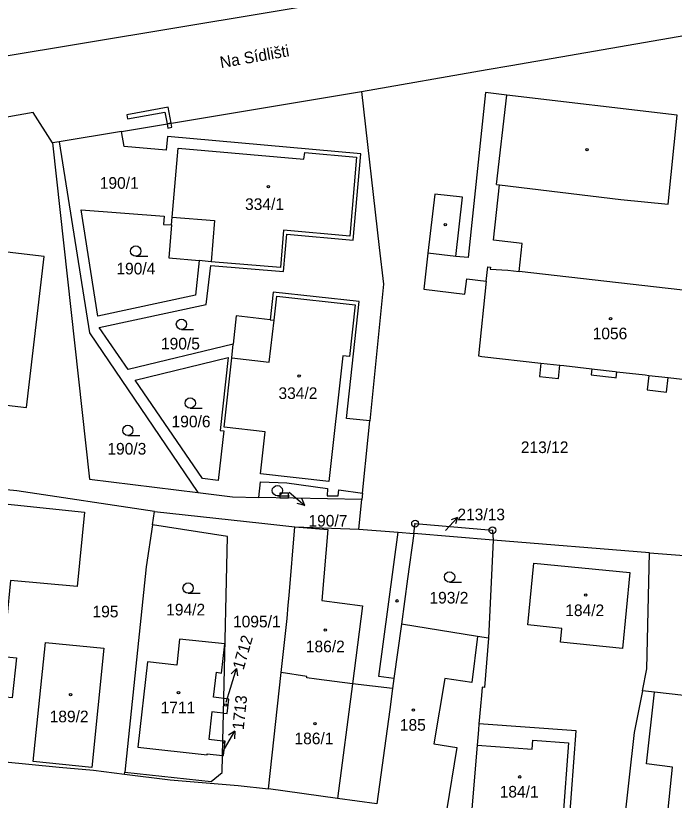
# Model space of a CAD drawing. Extents: x -680203 to -673936, y -1102717 to -1093650.
# Drawn here: x -679068.7 to -678972.5, y -1098436.4 to -1098321.8 of the extents above; entities that cross this region are included whole.
import ezdxf

# ---------------------------------------------------------------- set-up
doc = ezdxf.new("R2010")
doc.units = 0
for name, color, linetype in [('SOxx02xx_Koleje_param další_Popis10', 7, 'Continuous'), ('SOxx02xx_Staničení_Popis10', 7, 'Continuous'), ('SOxxxxxx_Koleje_hlavní_body_Popis10', 7, 'Continuous'), ('SOxxxxxx_Koleje_LN_parametry_Popis10', 7, 'Continuous'), ('SOxxxxxx_Koleje_param další_Popis10', 7, 'Continuous'), ('SOxxxxxx_Osa_bod_P', 7, 'Continuous'), ('SOxxxxxx_Staničení_Popis10', 7, 'Continuous'), ('x_prac', 7, 'Continuous')]:
    doc.layers.add(name, color=color, linetype=linetype)

msp = doc.modelspace()

# ---------------------------------------------------------------- linework, layer by layer
at = {"layer": 'SOxx02xx_Koleje_param další_Popis10'}
for centre, radius in [((-679010.34, -1098396.03), 0.5), ((-679010.34, -1098396.03), 0.0303), ((-678999.04, -1098396.99), 0.5), ((-678999.04, -1098396.99), 0.0303)]:
    msp.add_circle(centre, radius, dxfattribs=at)
at = {"layer": 'SOxx02xx_Staničení_Popis10'}
for p, q in [((-679028.73, -1098391.41), (-679026.46, -1098393.38)), ((-679026.46, -1098393.38), (-679027.55, -1098393.1)), ((-679026.46, -1098393.38), (-679026.89, -1098392.34)), ((-679005.89, -1098397.03), (-679004.16, -1098395.11)), ((-679004.16, -1098395.11), (-679005.06, -1098395.46)), ((-679004.16, -1098395.11), (-679004.42, -1098396.04)), ((-679037.32, -1098420.05), (-679036.44, -1098417.18)), ((-679036.44, -1098417.18), (-679037.21, -1098417.99)), ((-679036.44, -1098417.18), (-679036.26, -1098418.28)), ((-679037.96, -1098422.13), (-679037.32, -1098420.05)), ((-679038.17, -1098428.93), (-679036.67, -1098426.33)), ((-679036.67, -1098426.33), (-679037.6, -1098426.95)), ((-679036.67, -1098426.33), (-679036.74, -1098427.45)), ((-679038.38, -1098429.28), (-679038.17, -1098428.93))]:
    msp.add_line(p, q, dxfattribs=at)
at = {"layer": 'SOxxxxxx_Koleje_hlavní_body_Popis10'}
for p, q in [((-679051.15, -1098356.96), (-679049.4, -1098356.96)), ((-679044.47, -1098367.66), (-679042.72, -1098367.66)), ((-679043.18, -1098379.16), (-679041.43, -1098379.16)), ((-679052.3, -1098383.15), (-679050.55, -1098383.15)), ((-679030.46, -1098391.96), (-679028.71, -1098391.96)), ((-679005.3, -1098404.57), (-679003.55, -1098404.57)), ((-679043.5, -1098406.19), (-679041.75, -1098406.19))]:
    msp.add_line(p, q, dxfattribs=at)
for centre in [(-679051.15, -1098356.21), (-679044.47, -1098366.91), (-679043.18, -1098378.41), (-679052.3, -1098382.4), (-679030.46, -1098391.21), (-679005.3, -1098403.82), (-679043.5, -1098405.44)]:
    msp.add_circle(centre, 0.75, dxfattribs=at)
at = {"layer": 'SOxxxxxx_Koleje_LN_parametry_Popis10'}
for points in [[(-679046.89, -1098335.9), (-679046.56, -1098337.63), (-679045.97, -1098337.53), (-679046.41, -1098335.2), (-679052.46, -1098336.32), (-679052.35, -1098336.91)], [(-679046.56, -1098337.63), (-679046.45, -1098338.24), (-679045.86, -1098338.13), (-679045.97, -1098337.53)], [(-679028.85, -1098392.28), (-679028.85, -1098391.6), (-679030.12, -1098391.57), (-679030.12, -1098392.25)]]:
    msp.add_lwpolyline(points, close=True, dxfattribs=at)
at = {"layer": 'SOxxxxxx_Koleje_param další_Popis10'}
for centre, radius in [((-678985.22, -1098341.4), 0.175), ((-679031.77, -1098346.82), 0.175), ((-679005.94, -1098352.35), 0.175), ((-678981.8, -1098366.08), 0.175), ((-679027.28, -1098374.48), 0.175), ((-679012.98, -1098407.31), 0.175), ((-678985.42, -1098406.47), 0.175), ((-679023.47, -1098411.58), 0.175), ((-679060.67, -1098421.03), 0.175), ((-679044.9, -1098420.71), 0.175), ((-679038, -1098422.54), 0.175), ((-679010.59, -1098423.26), 0.175), ((-679024.97, -1098425.23), 0.175), ((-679038.27, -1098428.02), 0.117), ((-678995.06, -1098433.02), 0.175)]:
    msp.add_circle(centre, radius, dxfattribs=at)
at = {"layer": 'SOxxxxxx_Staničení_Popis10'}
for p, q in [((-678998.45, -1098346.51), (-678996.96, -1098333.42)), ((-678998.45, -1098346.51), (-678998.03, -1098346.56)), ((-679045.84, -1098351.25), (-679039.64, -1098351.77)), ((-679039.64, -1098351.77), (-679040.14, -1098357.76)), ((-679004.4, -1098356.99), (-679008.46, -1098356.53)), ((-678999.96, -1098360.61), (-678999.74, -1098358.5)), ((-678999.74, -1098358.5), (-678999.35, -1098358.54)), ((-678999.35, -1098358.54), (-678999.38, -1098358.84)), ((-678999.38, -1098358.84), (-678996.79, -1098359.01)), ((-678996.79, -1098359.01), (-678995.13, -1098359.2)), ((-679031.64, -1098372.44), (-679030.93, -1098366.31)), ((-679037.11, -1098371.83), (-679031.64, -1098372.44)), ((-678991.98, -1098372.57), (-678989.18, -1098372.89)), ((-678984.51, -1098373.42), (-678984.14, -1098373.46)), ((-678984.14, -1098373.46), (-678981.14, -1098373.8)), ((-678981.14, -1098373.8), (-678980.89, -1098373.83)), ((-678976.19, -1098374.37), (-678973.39, -1098374.69)), ((-679027.93, -1098396.48), (-679023.09, -1098396.88)), ((-679023.09, -1098396.88), (-679023.98, -1098407.26)), ((-679015.66, -1098418.35), (-679012.84, -1098397.28)), ((-678993.88, -1098410.83), (-678992.98, -1098401.79)), ((-678992.98, -1098401.79), (-678978.96, -1098403.19)), ((-678978.96, -1098403.19), (-678980.06, -1098414.26)), ((-679023.98, -1098407.26), (-679018.04, -1098408.05)), ((-679018.04, -1098408.05), (-679019.51, -1098419.41)), ((-678988.9, -1098411.33), (-678993.88, -1098410.83)), ((-678989.11, -1098413.35), (-678988.9, -1098411.33)), ((-679001.23, -1098412.51), (-679002.07, -1098419.22)), ((-678980.06, -1098414.26), (-678989.11, -1098413.35)), ((-679013.43, -1098418.65), (-679015.66, -1098418.35)), ((-679006.01, -1098418.67), (-679007.62, -1098428.18)), ((-679002.07, -1098419.22), (-679006.01, -1098418.67)), ((-679019.51, -1098419.41), (-679021.67, -1098436.17)), ((-678976.53, -1098431.13), (-678975.39, -1098420.63)), ((-679040.01, -1098423.52), (-679040.46, -1098427.53)), ((-679039.24, -1098423.6), (-679040.01, -1098423.52)), ((-679038.33, -1098423.71), (-679039.24, -1098423.6)), ((-679040.46, -1098427.53), (-679038.42, -1098427.76)), ((-678993.24, -1098428.96), (-678993.15, -1098427.66)), ((-678993.15, -1098427.66), (-678987.96, -1098428.03)), ((-679007.62, -1098428.18), (-679004.24, -1098428.75)), ((-679004.24, -1098428.75), (-679005.78, -1098437.99)), ((-679001.27, -1098428.38), (-678993.24, -1098428.96)), ((-678987.96, -1098428.03), (-678988.84, -1098439.94)), ((-678972.77, -1098431.58), (-678976.53, -1098431.13)), ((-678973.79, -1098441.67), (-678972.77, -1098431.58))]:
    msp.add_line(p, q, dxfattribs=at)
at = {"layer": 'x_prac'}
for p, q in [((-679053.23, -1098338.74), (-679018.19, -1098332.92)), ((-679053.23, -1098338.74), (-679062.31, -1098340.25)), ((-679062.31, -1098340.25), (-679063.29, -1098340.41)), ((-679018.12, -1098392.5), (-679033.18, -1098392.19)), ((-679018.03, -1098391.58), (-679018.12, -1098392.5)), ((-679018.55, -1098396.82), (-679018.12, -1098392.5)), ((-679048.69, -1098396.22), (-679048.39, -1098394.25)), ((-679027.93, -1098396.48), (-679018.55, -1098396.82)), ((-678998.95, -1098398.42), (-679010.54, -1098397.47)), ((-678998.95, -1098398.42), (-678999.64, -1098412.76)), ((-678976.11, -1098400.28), (-678998.95, -1098398.42)), ((-678976.11, -1098400.28), (-678962.43, -1098401.4)), ((-679031.77, -1098434.76), (-679029.91, -1098417.79)), ((-679038.33, -1098423.71), (-679038.28, -1098421.57)), ((-679038.42, -1098427.76), (-679038.33, -1098423.71)), ((-679038.47, -1098429.89), (-679038.42, -1098427.76)), ((-679052.8, -1098432.65), (-679052.76, -1098432.35))]:
    msp.add_line(p, q, dxfattribs=at)
for points in [[(-679019.35, -1098319.29), (-679071.6, -1098327.97), (-679120.11, -1098336.51)], [(-679018.19, -1098332.92), (-678999.8, -1098329.71), (-678996.35, -1098329.11), (-678970.78, -1098324.65), (-678966.75, -1098323.95), (-678958.79, -1098322.56)], [(-679018.19, -1098332.92), (-679015.58, -1098355.68), (-679014.97, -1098361.06), (-679016.97, -1098381.02)], [(-678966.15, -1098362.53), (-678995.13, -1098359.2), (-678994.69, -1098355.12), (-678998.9, -1098354.62), (-678998.03, -1098346.56), (-678980.27, -1098348.66), (-678973.36, -1098349.35), (-678972.06, -1098336.34), (-678996.96, -1098333.42), (-679000.04, -1098333.07), (-679001.05, -1098342.28), (-679002.6, -1098357.15), (-679004.4, -1098356.99), (-679003.43, -1098348.35)], [(-679063.29, -1098340.41), (-679066.13, -1098335.98), (-679082.06, -1098338.79), (-679101.3, -1098341.77), (-679136.96, -1098347.45), (-679149.82, -1098349.81), (-679185.71, -1098355.7), (-679199.74, -1098357.86), (-679234.17, -1098363.73), (-679248.19, -1098366.26), (-679260.56, -1098369.05), (-679268.5, -1098375.84), (-679272.26, -1098383.28), (-679273.78, -1098396.02), (-679274.25, -1098399.99), (-679276.49, -1098418.73), (-679277.09, -1098423.73)], [(-679036.9, -1098369.82), (-679052.24, -1098373.53), (-679056.47, -1098367.37), (-679040.85, -1098364.01), (-679040.2, -1098358.3), (-679029.56, -1098359.2), (-679029.06, -1098353.72), (-679019.39, -1098354.62), (-679018.29, -1098342.01), (-679046.52, -1098339.49), (-679046.68, -1098341.48), (-679052.86, -1098340.94), (-679053.23, -1098338.74)], [(-679063.29, -1098340.41), (-679057.92, -1098389.52), (-679042.06, -1098391.48)], [(-679062.31, -1098340.25), (-679057.92, -1098368.17), (-679042.06, -1098391.48)], [(-679045.93, -1098352.4), (-679045.84, -1098351.25), (-679044.96, -1098341.19), (-679026.59, -1098342.8), (-679026.47, -1098341.81), (-679018.88, -1098342.47), (-679019.89, -1098354.04), (-679029.55, -1098353.15), (-679029.99, -1098358.62), (-679040.14, -1098357.76), (-679041.87, -1098357.61)], [(-679003.43, -1098348.35), (-679007.47, -1098347.91), (-679008.46, -1098356.53), (-679009.09, -1098361.79), (-679003.06, -1098362.5), (-679002.81, -1098360.28), (-678999.96, -1098360.61), (-679001.08, -1098371.53), (-679000.59, -1098371.59), (-678991.98, -1098372.57), (-678992.16, -1098374.55), (-678989.41, -1098374.84), (-678989.18, -1098372.89), (-678988.63, -1098372.95), (-678984.51, -1098373.42), (-678984.61, -1098374.3), (-678984.24, -1098374.34), (-678981.24, -1098374.68), (-678980.97, -1098374.71), (-678980.89, -1098373.83), (-678976.72, -1098374.31), (-678976.19, -1098374.37), (-678976.43, -1098376.47), (-678973.62, -1098376.8), (-678973.39, -1098374.69), (-678964.69, -1098375.68)], [(-679041.87, -1098357.61), (-679042.4, -1098362.63), (-679056.69, -1098365.71), (-679059.12, -1098350.2), (-679047, -1098351.11), (-679047.08, -1098352.32), (-679045.93, -1098352.4)], [(-679045.93, -1098352.4), (-679046.33, -1098357.21), (-679041.87, -1098357.61)], [(-679081.54, -1098354.99), (-679084.22, -1098377.08), (-679067.08, -1098379.05), (-679064.54, -1098356.99), (-679081.54, -1098354.99)], [(-679016.97, -1098381.02), (-679020.35, -1098380.65), (-679018.49, -1098363.58), (-679031.05, -1098362.21), (-679031.5, -1098366.25)], [(-679031.5, -1098366.25), (-679030.93, -1098366.31), (-679030.54, -1098362.8), (-679019.08, -1098364.07), (-679019.92, -1098371.6), (-679020.91, -1098371.5), (-679022.95, -1098389.88), (-679032.94, -1098388.76), (-679032.26, -1098382.61), (-679038.24, -1098381.94), (-679037.11, -1098371.83), (-679036.9, -1098369.82)], [(-679031.5, -1098366.25), (-679036.48, -1098365.68), (-679036.9, -1098369.82)], [(-679038.3, -1098382.49), (-679039.09, -1098389.73), (-679041.38, -1098389.43), (-679051.22, -1098375.06), (-679037.66, -1098371.75), (-679038.82, -1098382.43), (-679038.3, -1098382.49)], [(-679018.03, -1098391.58), (-679017.21, -1098383.4), (-679016.97, -1098381.02)], [(-679033.18, -1098392.19), (-679032.9, -1098389.91), (-679029.07, -1098390.08), (-679023.12, -1098390.89), (-679023.18, -1098391.99), (-679021.58, -1098391.95), (-679021.49, -1098391.09), (-679018.03, -1098391.58)], [(-679048.39, -1098394.25), (-679068.5, -1098391.22), (-679079.62, -1098390.15)], [(-679070.53, -1098415.46), (-679068.58, -1098415.65), (-679069.2, -1098421.47), (-679071.08, -1098421.28), (-679071.99, -1098430.18), (-679082.77, -1098429.11), (-679079.11, -1098392.21), (-679058.62, -1098394.34), (-679059.69, -1098405.19), (-679069.43, -1098404.34), (-679070.53, -1098415.46)], [(-679042.06, -1098391.48), (-679037.01, -1098392.11), (-679033.18, -1098392.19)], [(-679048.39, -1098394.25), (-679032.72, -1098395.95), (-679027.93, -1098396.48)], [(-679048.69, -1098396.22), (-679049.6, -1098402.33), (-679050.87, -1098414.49), (-679052.76, -1098432.35)], [(-679038.28, -1098421.57), (-679037.73, -1098397.93), (-679048.69, -1098396.22)], [(-679029.91, -1098417.79), (-679029.04, -1098409.89), (-679028.88, -1098407.94), (-679028.76, -1098406.55), (-679027.93, -1098396.48)], [(-679018.55, -1098396.82), (-679012.84, -1098397.28), (-679010.54, -1098397.47)], [(-679010.54, -1098397.47), (-679010.34, -1098396.03), (-678999.04, -1098396.99), (-678998.95, -1098398.42)], [(-679010.54, -1098397.47), (-679011.44, -1098404.07), (-679012.35, -1098410.71)], [(-678977.14, -1098420.43), (-678976.52, -1098417.24), (-678976.11, -1098400.28)], [(-679012.35, -1098410.71), (-679013.43, -1098418.65), (-679013.63, -1098420.13)], [(-678999.64, -1098412.76), (-679001.23, -1098412.51), (-679012.35, -1098410.71)], [(-679038.28, -1098421.57), (-679039.01, -1098421.49), (-679039.77, -1098421.4), (-679039.36, -1098417.75), (-679038.6, -1098417.85), (-679038.13, -1098413.6), (-679044.74, -1098412.91), (-679045.16, -1098416.69), (-679049.44, -1098416.22), (-679050.84, -1098428.66), (-679040.72, -1098429.78), (-679040.7, -1098429.64), (-679038.47, -1098429.89)], [(-678999.64, -1098412.76), (-679000.2, -1098419.97), (-679000.57, -1098419.94), (-679000.66, -1098421.13), (-679000.8, -1098422.7), (-679001.01, -1098425.26)], [(-679055.81, -1098414.24), (-679057.57, -1098431.63), (-679066.11, -1098430.79), (-679064.35, -1098413.37), (-679055.81, -1098414.24)], [(-679013.63, -1098420.13), (-679019.51, -1098419.41), (-679024.73, -1098418.77), (-679026.18, -1098418.57), (-679026.16, -1098418.38), (-679029.91, -1098417.79)], [(-679013.63, -1098420.13), (-679014.05, -1098423.2), (-679015.93, -1098436.98)], [(-678977.14, -1098420.43), (-678978.34, -1098426.56), (-678979.95, -1098440.9)], [(-678964.23, -1098421.89), (-678975.39, -1098420.63), (-678977.14, -1098420.43)], [(-679038.33, -1098423.71), (-679037.81, -1098423.77), (-679037.57, -1098421.65), (-679038.28, -1098421.57)], [(-679001.01, -1098425.26), (-679001.08, -1098426.16), (-679001.27, -1098428.38), (-679002.14, -1098438.85)], [(-678987.85, -1098440.04), (-678986.83, -1098426.31), (-679001.01, -1098425.26)], [(-679038.47, -1098429.89), (-679038.31, -1098429.9), (-679038.07, -1098427.8), (-679038.42, -1098427.76)], [(-679083.44, -1098429.53), (-679074.72, -1098430.41), (-679062.34, -1098431.59), (-679057.33, -1098432.02), (-679052.8, -1098432.65)], [(-679052.76, -1098432.35), (-679040.12, -1098433.68), (-679038.53, -1098432.4), (-679038.47, -1098429.89)], [(-679052.8, -1098432.65), (-679046.13, -1098433.47), (-679036.19, -1098434.29), (-679031.77, -1098434.76)], [(-679015.93, -1098436.98), (-679021.67, -1098436.17), (-679031.77, -1098434.76)]]:
    msp.add_lwpolyline(points, dxfattribs=at)

# ---------------------------------------------------------------- texts
at = {"layer": 'SOxx02xx_Staničení_Popis10'}
msp.add_text('Na Sídlišti', height=1.7, rotation=10, dxfattribs=at).set_placement((-679038.69, -1098329.51))
at = {"layer": 'SOxxxxxx_Osa_bod_P'}
for s, p in [('190/1', (-679056.4, -1098347.11)), ('334/1', (-679035.18, -1098350.21)), ('190/4', (-679053.97, -1098359.62)), ('1056', (-678984.41, -1098369.1)), ('190/5', (-679047.46, -1098370.58)), ('334/2', (-679030.3, -1098377.82)), ('190/6', (-679045.91, -1098381.96)), ('190/3', (-679055.29, -1098385.94)), ('213/12', (-678994.9, -1098385.72)), ('213/13', (-679004.17, -1098395.54)), ('190/7', (-679025.92, -1098396.46)), ('193/2', (-679008.25, -1098407.7)), ('195', (-679057.46, -1098409.72)), ('194/2', (-679046.7, -1098409.44)), ('184/2', (-678988.41, -1098409.54)), ('1095/1', (-679036.94, -1098411.18)), ('186/2', (-679026.3, -1098414.82)), ('1711', (-679047.51, -1098423.74)), ('189/2', (-679063.72, -1098425.05)), ('185', (-679012.57, -1098426.28)), ('186/1', (-679027.96, -1098428.26)), ('184/1', (-678997.99, -1098436.04))]:
    msp.add_text(s, height=1.7, dxfattribs=at).set_placement(p)
for s, rotation, p in [('1712', 74, (-679035.4, -1098417.49)), ('1713', 84, (-679035.38, -1098426.22))]:
    msp.add_text(s, height=1.7, rotation=rotation, dxfattribs=at).set_placement(p)

doc.saveas('drawing.dxf')
